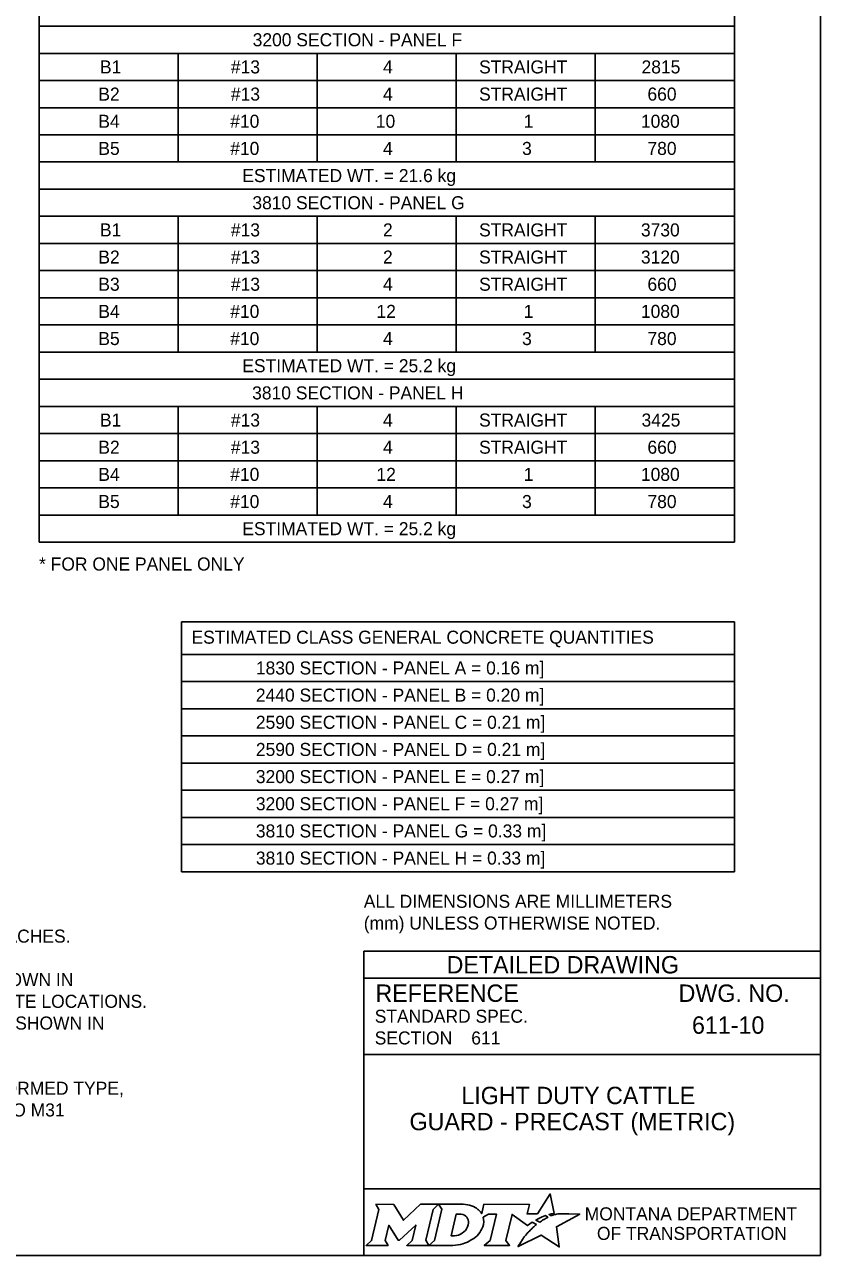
# Model space of a CAD drawing. Extents: x 49991.4 to 50021, y 49987.6 to 50011.4.
# Drawn here: x 50013.09 to 50016.75, y 49987.8 to 49993.46 of the extents above; entities that cross this region are included whole.
import ezdxf

# ---------------------------------------------------------------- set-up
doc = ezdxf.new("R2010")
doc.units = 0
for name, color, linetype in [('Default', 7, 'Continuous'), ('Level 1', 7, 'Continuous'), ('Level 2', 7, 'Continuous'), ('Level 5', 7, 'Continuous')]:
    doc.layers.add(name, color=color, linetype=linetype)

msp = doc.modelspace()

# ---------------------------------------------------------------- linework, layer by layer
at = {"layer": 'Default'}
for points in [[(50015.5126, 49987.9811), (50015.5023, 49987.9867), (50015.5139, 49987.9895), (50015.5255, 49987.9915), (50015.5081, 49988.0816), (50015.4486, 49987.9903), (50015.4013, 49987.9896), (50015.4116, 49988.0337), (50015.2024, 49988.0338), (50015.1923, 49987.9913), (50015.1865, 49987.9996)], [(50014.7056, 49988.0338), (50014.7197, 49988.0104), (50014.6862, 49987.8671), (50014.6605, 49987.8446), (50014.7621, 49987.8446), (50014.7486, 49987.8674), (50014.7648, 49987.9375), (50014.8085, 49987.8685), (50014.8138, 49987.8685), (50014.8889, 49987.938), (50014.8725, 49987.8669), (50014.8478, 49987.8449), (50014.9494, 49987.8449), (50014.9356, 49987.8682), (50014.9688, 49988.0106)], [(50014.9688, 49988.0106), (50014.9941, 49988.0338), (50014.9117, 49988.0338), (50014.8321, 49987.9608), (50014.7876, 49988.0335), (50014.7056, 49988.0338)], [(50015.1077, 49988.0338), (50014.9941, 49988.0338), (50015.0088, 49988.0109), (50014.9749, 49987.8671), (50014.9494, 49987.8449), (50015.06, 49987.8449)], [(50015.1317, 49987.9471), (50015.1305, 49987.939), (50015.1273, 49987.9297), (50015.1231, 49987.9215), (50015.1175, 49987.914), (50015.111, 49987.9071), (50015.1031, 49987.9008), (50015.0948, 49987.8961), (50015.0857, 49987.8922), (50015.0766, 49987.8899), (50015.0674, 49987.889), (50015.0515, 49987.889), (50015.0751, 49987.989), (50015.0911, 49987.989), (50015.0987, 49987.9884), (50015.1063, 49987.9865), (50015.1129, 49987.9835), (50015.119, 49987.9793), (50015.1238, 49987.9743), (50015.1275, 49987.9683), (50015.1302, 49987.9621), (50015.1318, 49987.9547), (50015.1318, 49987.9517), (50015.1317, 49987.9471)], [(50015.1991, 49987.9747), (50015.2237, 49987.9878), (50015.2606, 49987.9878), (50015.232, 49987.8673), (50015.2045, 49987.8446), (50015.3207, 49987.8446), (50015.3037, 49987.8675), (50015.3319, 49987.9877), (50015.4032, 49987.936), (50015.4243, 49987.9511), (50015.444, 49987.9402)], [(50015.3882, 49987.8843), (50015.3729, 49987.8599), (50015.3682, 49987.8524), (50015.3624, 49987.8438), (50015.3601, 49987.8395), (50015.4654, 49987.8926), (50015.5493, 49987.8375), (50015.5362, 49987.9302), (50015.6431, 49987.9886), (50015.5938, 49987.9894), (50015.5637, 49987.9898), (50015.5429, 49987.9901), (50015.5361, 49987.9886), (50015.5312, 49987.9874), (50015.5228, 49987.9851), (50015.5126, 49987.9811)], [(50015.4622, 49987.9535), (50015.4598, 49987.9518), (50015.4415, 49987.9614), (50015.4518, 49987.9671), (50015.4559, 49987.9693), (50015.4645, 49987.9733), (50015.4702, 49987.9759), (50015.4781, 49987.9789), (50015.4854, 49987.9816), (50015.4972, 49987.9742), (50015.4932, 49987.9721), (50015.4886, 49987.9696), (50015.4844, 49987.9674), (50015.4794, 49987.9645), (50015.4775, 49987.9634), (50015.4748, 49987.9618), (50015.4723, 49987.9604), (50015.47, 49987.9588), (50015.4674, 49987.957), (50015.4647, 49987.9552), (50015.4622, 49987.9535)], [(50015.4021, 49987.9004), (50015.4021, 49987.9004)], [(50015.1057, 49987.8522), (50015.1141, 49987.8548), (50015.1271, 49987.8602), (50015.1475, 49987.8712)]]:
    msp.add_lwpolyline(points, dxfattribs=at)
for centre, radius, start, end in [((50015.1308, 49987.9554), 0.0709, 339.5329, 15.8582), ((50015.0868, 49987.9727), 0.1183, 300.9103, 339.1383)]:
    msp.add_arc(centre, radius, start, end, dxfattribs=at)
for centre, major_axis, ratio, start_param, end_param in [((50015.1056, 49987.9864), (0.0834, -0.0037), 0.568097, 0.61298, 1.570796), ((50015.1612, 49987.9937), (0.0361, -0.0295), 0.469099, 1.225588, 1.570796), ((50015.3952, 49987.8923), (-0.00694, -0.00806), 0.008222, 0, 3.137361), ((50015.4119, 49987.9106), (-0.0098, -0.0102), 0.016458, 3.141593, 6.279097), ((50015.4329, 49987.9305), (-0.0112, -0.0097), 0.021651, 3.157348, 6.283185), ((50015.0603, 49987.9932), (0, 0.1484), 0.987302, 3.139398, 3.456847)]:
    msp.add_ellipse(centre, major_axis=major_axis, ratio=ratio, start_param=start_param, end_param=end_param, dxfattribs=at)
at = {"layer": 'Level 1'}
msp.add_lwpolyline([(49999.3835, 49998.9992), (50016.7501, 49998.9992), (50016.7501, 49987.7988), (49999.3835, 49987.7988)], close=True, dxfattribs=at)
at = {"layer": 'Level 2'}
for p, q in [((50013.1565, 49991.0805), (50013.1565, 49998.6599)), ((50016.3545, 49991.0805), (50016.3545, 49998.6599)), ((50016.3545, 49993.4555), (50013.1565, 49993.4555)), ((50016.3545, 49993.3305), (50013.1565, 49993.3305)), ((50013.7961, 49992.8305), (50013.7961, 49993.3305)), ((50014.4357, 49992.8305), (50014.4357, 49993.3305)), ((50015.0753, 49992.8305), (50015.0753, 49993.3305)), ((50015.7149, 49992.8305), (50015.7149, 49993.3305)), ((50016.3545, 49993.2055), (50013.1565, 49993.2055)), ((50016.3545, 49993.0805), (50013.1565, 49993.0805)), ((50016.3545, 49992.9555), (50013.1565, 49992.9555)), ((50016.3545, 49992.8305), (50013.1565, 49992.8305)), ((50016.3545, 49992.7055), (50013.1565, 49992.7055)), ((50016.3545, 49992.5805), (50013.1565, 49992.5805)), ((50013.7961, 49991.9555), (50013.7961, 49992.5805)), ((50014.4357, 49991.9555), (50014.4357, 49992.5805)), ((50015.0753, 49991.9555), (50015.0753, 49992.5805)), ((50015.7149, 49991.9555), (50015.7149, 49992.5805)), ((50016.3545, 49992.4555), (50013.1565, 49992.4555)), ((50016.3545, 49992.3305), (50013.1565, 49992.3305)), ((50016.3545, 49992.2055), (50013.1565, 49992.2055)), ((50016.3545, 49992.0805), (50013.1565, 49992.0805)), ((50016.3545, 49991.9555), (50013.1565, 49991.9555)), ((50016.3545, 49991.8305), (50013.1565, 49991.8305)), ((50016.3545, 49991.7055), (50013.1565, 49991.7055)), ((50013.7961, 49991.2055), (50013.7961, 49991.7055)), ((50014.4357, 49991.2055), (50014.4357, 49991.7055)), ((50015.0753, 49991.2055), (50015.0753, 49991.7055)), ((50015.7149, 49991.2055), (50015.7149, 49991.7055)), ((50016.3545, 49991.5805), (50013.1565, 49991.5805)), ((50016.3545, 49991.4555), (50013.1565, 49991.4555)), ((50016.3545, 49991.3305), (50013.1565, 49991.3305)), ((50016.3545, 49991.2055), (50013.1565, 49991.2055)), ((50016.3545, 49991.0805), (50013.1565, 49991.0805)), ((50016.3545, 49990.7146), (50013.8124, 49990.7146)), ((50013.8124, 49990.7146), (50013.8124, 49989.5646)), ((50016.3545, 49989.5646), (50016.3545, 49990.7146)), ((50016.3545, 49990.5646), (50013.8124, 49990.5646)), ((50016.3545, 49990.4396), (50013.8124, 49990.4396)), ((50016.3545, 49990.3146), (50013.8124, 49990.3146)), ((50016.3545, 49990.1896), (50013.8124, 49990.1896)), ((50016.3545, 49990.0646), (50013.8124, 49990.0646)), ((50016.3545, 49989.9396), (50013.8124, 49989.9396)), ((50016.3545, 49989.8146), (50013.8124, 49989.8146)), ((50016.3545, 49989.6896), (50013.8124, 49989.6896)), ((50016.3545, 49989.5646), (50013.8124, 49989.5646))]:
    msp.add_line(p, q, dxfattribs=at)
at = {"layer": 'Level 5'}
for p, q in [((50016.7501, 49989.1988), (50014.6501, 49989.1988)), ((50014.6501, 49989.1988), (50014.6501, 49987.7988)), ((50016.7501, 49989.0738), (50014.6501, 49989.0738)), ((50016.3862, 49988.8587), (50016.3862, 49988.8587)), ((50015.1444, 49988.7993), (50015.1444, 49988.7993)), ((50016.7501, 49988.7238), (50014.6501, 49988.7238)), ((50015.7001, 49988.4747), (50015.7001, 49988.4747)), ((50016.7501, 49988.1057), (50014.6501, 49988.1057))]:
    msp.add_line(p, q, dxfattribs=at)

# ---------------------------------------------------------------- texts
at = {"layer": 'Default'}
for s, p in [('MONTANA DEPARTMENT', (50015.6663, 49987.96)), ('OF TRANSPORTATION', (50015.7225, 49987.87))]:
    msp.add_text(s, height=0.06, dxfattribs=at).set_placement(p)
at = {"layer": 'Level 2'}
for s, height, p in [('3200 SECTION - PANEL F', 0.06, (50014.1391, 49993.363)), ('B1', 0.06, (50013.4367, 49993.238)), ('#13', 0.06, (50014.0389, 49993.238)), ('4', 0.06, (50014.7385, 49993.238)), ('STRAIGHT', 0.06, (50015.1804, 49993.238)), ('2815', 0.06, (50015.9277, 49993.238)), ('B2', 0.06, (50013.4293, 49993.113)), ('#13', 0.06, (50014.0389, 49993.113)), ('4', 0.06, (50014.7385, 49993.113)), ('STRAIGHT', 0.06, (50015.1804, 49993.113)), ('660', 0.06, (50015.9548, 49993.113)), ('B4', 0.06, (50013.4293, 49992.988)), ('#10', 0.06, (50014.0359, 49992.988)), ('10', 0.06, (50014.7055, 49992.988)), ('1', 0.06, (50015.3855, 49992.988)), ('1080', 0.06, (50015.9248, 49992.988)), ('B5', 0.06, (50013.4293, 49992.863)), ('#10', 0.06, (50014.0359, 49992.863)), ('4', 0.06, (50014.7385, 49992.863)), ('3', 0.06, (50015.3781, 49992.863)), ('780', 0.06, (50015.9548, 49992.863)), ('ESTIMATED WT. = 21.6 kg', 0.06, (50014.0914, 49992.738)), ('3810 SECTION - PANEL G', 0.06, (50014.1377, 49992.613)), ('B1', 0.06, (50013.4367, 49992.488)), ('#13', 0.06, (50014.0389, 49992.488)), ('2', 0.06, (50014.7385, 49992.488)), ('STRAIGHT', 0.06, (50015.1804, 49992.488)), ('3730', 0.06, (50015.9248, 49992.488)), ('B2', 0.06, (50013.4293, 49992.363)), ('#13', 0.06, (50014.0389, 49992.363)), ('2', 0.06, (50014.7385, 49992.363)), ('STRAIGHT', 0.06, (50015.1804, 49992.363)), ('3120', 0.06, (50015.9248, 49992.363)), ('B3', 0.06, (50013.4293, 49992.238)), ('#13', 0.06, (50014.0389, 49992.238)), ('4', 0.06, (50014.7385, 49992.238)), ('STRAIGHT', 0.06, (50015.1804, 49992.238)), ('660', 0.06, (50015.9548, 49992.238)), ('B4', 0.06, (50013.4293, 49992.113)), ('#10', 0.06, (50014.0359, 49992.113)), ('12', 0.06, (50014.7085, 49992.113)), ('1', 0.06, (50015.3855, 49992.113)), ('1080', 0.06, (50015.9248, 49992.113)), ('B5', 0.06, (50013.4293, 49991.988)), ('#10', 0.06, (50014.0359, 49991.988)), ('4', 0.06, (50014.7385, 49991.988)), ('3', 0.06, (50015.3781, 49991.988)), ('780', 0.06, (50015.9548, 49991.988)), ('ESTIMATED WT. = 25.2 kg', 0.06, (50014.0914, 49991.863)), ('3810 SECTION - PANEL H', 0.06, (50014.1367, 49991.738)), ('B1', 0.06, (50013.4367, 49991.613)), ('#13', 0.06, (50014.0389, 49991.613)), ('4', 0.06, (50014.7385, 49991.613)), ('STRAIGHT', 0.06, (50015.1804, 49991.613)), ('3425', 0.06, (50015.9277, 49991.613)), ('B2', 0.06, (50013.4293, 49991.488)), ('#13', 0.06, (50014.0389, 49991.488)), ('4', 0.06, (50014.7385, 49991.488)), ('STRAIGHT', 0.06, (50015.1804, 49991.488)), ('660', 0.06, (50015.9548, 49991.488)), ('B4', 0.06, (50013.4293, 49991.363)), ('#10', 0.06, (50014.0359, 49991.363)), ('12', 0.06, (50014.7085, 49991.363)), ('1', 0.06, (50015.3855, 49991.363)), ('1080', 0.06, (50015.9248, 49991.363)), ('B5', 0.06, (50013.4293, 49991.238)), ('#10', 0.06, (50014.0359, 49991.238)), ('4', 0.06, (50014.7385, 49991.238)), ('3', 0.06, (50015.3781, 49991.238)), ('780', 0.06, (50015.9548, 49991.238)), ('ESTIMATED WT. = 25.2 kg', 0.06, (50014.0914, 49991.113)), ('* FOR ONE PANEL ONLY', 0.06, (50013.1565, 49990.9505)), ('ESTIMATED CLASS GENERAL CONCRETE QUANTITIES', 0.06, (50013.8576, 49990.6137)), ('1830 SECTION - PANEL A = 0.16 m]', 0.06, (50014.1538, 49990.4721)), ('2440 SECTION - PANEL B = 0.20 m]', 0.06, (50014.1538, 49990.3471)), ('2590 SECTION - PANEL C = 0.21 m]', 0.06, (50014.1538, 49990.2221)), ('2590 SECTION - PANEL D = 0.21 m]', 0.06, (50014.1538, 49990.0971)), ('3200 SECTION - PANEL E = 0.27 m]', 0.06, (50014.1538, 49989.9721)), ('3200 SECTION - PANEL F = 0.27 m]', 0.06, (50014.1538, 49989.8471)), ('3810 SECTION - PANEL G = 0.33 m]', 0.06, (50014.1538, 49989.7221)), ('3810 SECTION - PANEL H = 0.33 m]', 0.06, (50014.1538, 49989.5971)), ('ALL DIMENSIONS ARE MILLIMETERS', 0.06, (50014.6501, 49989.3983)), ('(mm) UNLESS OTHERWISE NOTED.', 0.06, (50014.6501, 49989.2983)), ('USE ONLY ON FIELD OR PRIVATE APPROACHES.', 0.06, (50011.393, 49989.238)), ('PROVIDE CAST-IN ANCHOR BOLTS AS SHOWN IN', 0.06, (50011.393, 49989.038)), ('DTL. DWG. NO. 611-00 AT THE APPROPRIATE LOCATIONS.', 0.06, (50011.393, 49988.938)), ('CAST-IN LAG PLATES, SIMILAR TO THOSE SHOWN IN', 0.06, (50011.393, 49988.838)), ('611-10', 0.08, (50016.1596, 49988.8187)), ('611', 0.06, (50015.1444, 49988.7693)), ('ALL REINFORCING STEEL IS OF THE DEFORMED TYPE,', 0.06, (50011.393, 49988.538)), ('LIGHT DUTY CATTLE', 0.08, (50015.0988, 49988.4947)), ('MEETING THE REQUIREMENTS OF AASHTO M31', 0.06, (50011.393, 49988.438)), ('GUARD - PRECAST (METRIC)', 0.08, (50014.8603, 49988.3747))]:
    msp.add_text(s, height=height, dxfattribs=at).set_placement(p)
at = {"layer": 'Level 5'}
for s, height, p in [('DETAILED DRAWING', 0.0799, (50015.0311, 49989.0963)), ('REFERENCE', 0.08, (50014.7037, 49988.9654)), ('DWG. NO.', 0.08, (50016.0979, 49988.9654)), ('STANDARD SPEC.', 0.06, (50014.7004, 49988.8694)), ('SECTION', 0.06, (50014.7004, 49988.7694))]:
    msp.add_text(s, height=height, dxfattribs=at).set_placement(p)

doc.saveas('drawing.dxf')
